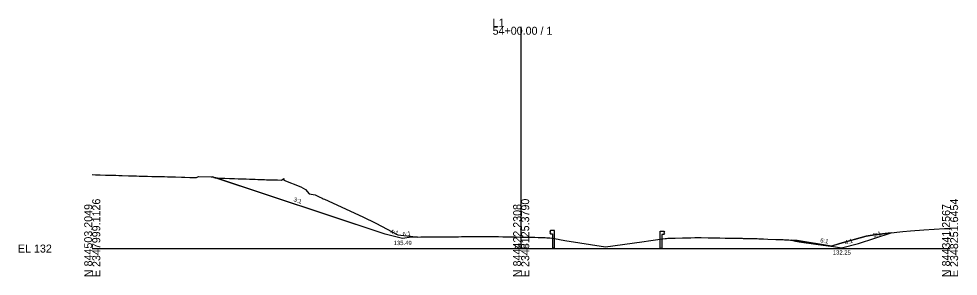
# Model space of a CAD drawing. Extents: x -26 to 2348258, y -10 to 844496.
# Drawn here: x 1275.5 to 1604, y 4990.3 to 5080.5 of the extents above; entities that cross this region are included whole.
import ezdxf

# ---------------------------------------------------------------- set-up
doc = ezdxf.new("R2010")
doc.units = 0
for name, color, linetype in [('Exist Cross Section Cell', 7, 'Continuous'), ('Exist XS Center Line Elevation Label', 7, 'Continuous'), ('Exist XS Ground Line', 7, 'Continuous'), ('Prop CMT Guardrail Graphics', 7, 'Continuous'), ('Prop CMT Slope Grass', 7, 'Continuous'), ('Prop XS Earthwork Shape', 7, 'Continuous'), ('Prop XS SE Text', 7, 'Continuous')]:
    doc.layers.add(name, color=color, linetype=linetype)

msp = doc.modelspace()

# ---------------------------------------------------------------- linework, layer by layer
at = {"layer": 'Exist Cross Section Cell'}
for p, q in [((1451.19, 5000), (1451.19, 5077.7)), ((1301.19, 5000), (1451.19, 5000)), ((1451.19, 5000), (1601.19, 5000))]:
    msp.add_line(p, q, dxfattribs=at)
at = {"layer": 'Exist XS Ground Line'}
msp.add_lwpolyline([(1301.19, 5025.9), (1302.3, 5025.85), (1302.75, 5025.84), (1303.97, 5025.8), (1305.82, 5025.75), (1307.57, 5025.71), (1308.7, 5025.68), (1309.39, 5025.66), (1310.47, 5025.63), (1311.67, 5025.6), (1313.87, 5025.52), (1315.06, 5025.48), (1316.61, 5025.44), (1317.58, 5025.41), (1318.36, 5025.39), (1319.12, 5025.37), (1320.55, 5025.34), (1322.02, 5025.3), (1323.51, 5025.27), (1323.85, 5025.26), (1324.37, 5025.25), (1326.51, 5025.2), (1327.46, 5025.16), (1328.95, 5025.12), (1329.46, 5025.1), (1330.36, 5025.07), (1332.44, 5025.01), (1332.87, 5025.01), (1333.61, 5024.99), (1335.35, 5024.95), (1336.61, 5024.93), (1337.2, 5024.93), (1337.68, 5024.92), (1338.32, 5025.25), (1342.79, 5025.16), (1343.47, 5025.14), (1344.16, 5024.73), (1344.95, 5024.72), (1345.83, 5024.69), (1347.51, 5024.62), (1349.18, 5024.56), (1350.22, 5024.53), (1350.97, 5024.51), (1352.17, 5024.47), (1353.19, 5024.43), (1355.01, 5024.38), (1356.15, 5024.35), (1356.77, 5024.32), (1358.22, 5024.27), (1359.14, 5024.24), (1361.41, 5024.15), (1362.1, 5024.12), (1363.63, 5024.08), (1365.07, 5024.04), (1365.92, 5024.03), (1367.37, 5024.01), (1368.19, 5024.6), (1368.2, 5023.99), (1374.1, 5021.58), (1375.79, 5020.64), (1377.02, 5019.23), (1379.2, 5018.83), (1380.56, 5018.15), (1381.55, 5017.65), (1382, 5017.45), (1382.36, 5017.27), (1395.77, 5011.07), (1400.35, 5008.86), (1408.08, 5004.81), (1413.27, 5004.27), (1414.88, 5004.03), (1416.15, 5004.06), (1417, 5004.07), (1418.56, 5004.08), (1421.6, 5004.1), (1424.54, 5004.12), (1425.19, 5004.12), (1426.32, 5004.13), (1427.21, 5004.14), (1427.57, 5004.14), (1429.28, 5004.16), (1430.37, 5004.17), (1430.92, 5004.17), (1432.41, 5004.19), (1433.41, 5004.19), (1435.51, 5004.2), (1436.4, 5004.21), (1437.84, 5004.22), (1439.78, 5004.21), (1440.82, 5004.2), (1442.28, 5004.19), (1443.25, 5004.17), (1444.77, 5004.15), (1445.27, 5004.15), (1446.14, 5004.13), (1448.22, 5004.08), (1449.43, 5004.06), (1450.87, 5004.03), (1451.27, 5004.02), (1454.16, 5003.97), (1455.91, 5003.94), (1457.14, 5003.91), (1457.74, 5003.9), (1458.72, 5003.87), (1459.57, 5003.84), (1460.16, 5003.81), (1461.19, 5003.78), (1464.16, 5003.26), (1464.54, 5003.19), (1466.41, 5002.87), (1480.64, 5000.55), (1493.41, 5002.41), (1496.53, 5002.84), (1498.17, 5003.1), (1501.53, 5003.57), (1502.01, 5003.56), (1502.47, 5003.59), (1502.93, 5003.61), (1504.76, 5003.66), (1505.08, 5003.67), (1507.61, 5003.74), (1508.42, 5003.76), (1509.72, 5003.79), (1510.25, 5003.8), (1510.58, 5003.8), (1511.92, 5003.82), (1513.15, 5003.82), (1513.75, 5003.82), (1514.18, 5003.82), (1516.59, 5003.8), (1518.84, 5003.77), (1519.54, 5003.75), (1520.71, 5003.73), (1522.49, 5003.7), (1523.79, 5003.66), (1524.12, 5003.66), (1525.46, 5003.64), (1526.5, 5003.62), (1528.45, 5003.59), (1528.86, 5003.58), (1531.37, 5003.53), (1531.89, 5003.51), (1532.82, 5003.49), (1533.78, 5003.47), (1534.36, 5003.45), (1535.89, 5003.44), (1537.49, 5003.34), (1540.26, 5003.23), (1540.94, 5003.2), (1542.09, 5003.15), (1542.85, 5003.12), (1543.29, 5003.1), (1544.74, 5003.03), (1545.35, 5003), (1545.71, 5002.99), (1547.12, 5002.64), (1548.45, 5002.31), (1555.05, 5001.41), (1559.49, 5000.79), (1562.66, 5001.75), (1571.82, 5004.31), (1575.43, 5004.96), (1584.71, 5006), (1587.31, 5006.26), (1591.97, 5006.54), (1599.19, 5007.02), (1601.19, 5007.05)], dxfattribs=at)
at = {"layer": 'Prop CMT Guardrail Graphics'}
for p, q in [((1461.46, 5006.28), (1461.19, 5005.99)), ((1461.19, 5005.99), (1461.46, 5005.7)), ((1461.46, 5005.7), (1461.19, 5005.41)), ((1461.19, 5005.41), (1461.46, 5005.11)), ((1462.79, 5006.28), (1461.46, 5006.28)), ((1461.46, 5005.11), (1462.13, 5005.11)), ((1462.13, 5005.11), (1462.13, 5000.28)), ((1462.79, 5000.28), (1462.79, 5006.28)), ((1499.77, 5000.04), (1499.77, 5006.04)), ((1499.77, 5006.04), (1501.1, 5006.04)), ((1501.1, 5004.88), (1500.43, 5004.88)), ((1500.43, 5004.88), (1500.43, 5000.04)), ((1501.1, 5006.04), (1501.37, 5005.75)), ((1501.37, 5005.75), (1501.1, 5005.46)), ((1501.1, 5005.46), (1501.37, 5005.17)), ((1501.37, 5005.17), (1501.1, 5004.88)), ((1462.13, 5000.28), (1462.79, 5000.28)), ((1500.43, 5000.04), (1499.77, 5000.04))]:
    msp.add_line(p, q, dxfattribs=at)
at = {"layer": 'Prop CMT Slope Grass'}
for p, q in [((1403.65, 5004.99), (1343.17, 5025.15)), ((1409.65, 5003.49), (1403.65, 5004.99)), ((1412.88, 5004.03), (1409.65, 5003.49)), ((1414.88, 5004.03), (1412.88, 5004.03)), ((1569.21, 5001.75), (1580.55, 5005.53)), ((1545.71, 5002.99), (1547.71, 5002.83)), ((1547.71, 5002.83), (1563.21, 5000.25)), ((1563.21, 5000.25), (1569.21, 5001.75))]:
    msp.add_line(p, q, dxfattribs=at)
at = {"layer": 'Prop XS Earthwork Shape'}
for points in [[(1343.47, 5025.14), (1343.83, 5024.93), (1343.17, 5025.15)], [(1344.16, 5024.73), (1344.43, 5024.73), (1343.83, 5024.93)], [(1355.01, 5024.38), (1356.15, 5024.35), (1356.77, 5024.32), (1358.22, 5024.27), (1359.14, 5024.24), (1361.41, 5024.15), (1362.1, 5024.12), (1363.63, 5024.08), (1365.07, 5024.04), (1365.92, 5024.03), (1367.37, 5024.01), (1368.19, 5024.6), (1368.2, 5023.99), (1374.1, 5021.58), (1375.79, 5020.64), (1377.02, 5019.23), (1379.2, 5018.83), (1380.56, 5018.15), (1381.55, 5017.65), (1382, 5017.45), (1382.36, 5017.27), (1395.77, 5011.07), (1400.35, 5008.86), (1408.08, 5004.81), (1413.27, 5004.27), (1414.88, 5004.03), (1412.88, 5004.03), (1409.65, 5003.49), (1403.65, 5004.99), (1344.43, 5024.73), (1344.95, 5024.72), (1345.83, 5024.69), (1347.51, 5024.62), (1349.18, 5024.56), (1350.22, 5024.53), (1350.97, 5024.51), (1352.17, 5024.47), (1353.19, 5024.43)], [(1569.21, 5001.75), (1580.55, 5005.53), (1575.43, 5004.96), (1571.82, 5004.31), (1562.66, 5001.75), (1559.66, 5000.84), (1563.21, 5000.25)], [(1548.45, 5002.31), (1555.05, 5001.41), (1559.49, 5000.79), (1559.66, 5000.84), (1547.71, 5002.83), (1545.71, 5002.99), (1547.12, 5002.64)]]:
    msp.add_lwpolyline(points, close=True, dxfattribs=at)

# ---------------------------------------------------------------- texts
at = {"layer": 'Exist Cross Section Cell'}
for s, p in [('L1', (1441.19, 5077.7)), ('54+00.00 / 1', (1441.19, 5074.9)), ('EL 132', (1275.19, 4998.6))]:
    msp.add_text(s, height=2.8, dxfattribs=at).set_placement(p)
for s, p in [('E 2347999.1126', (1303.99, 4990)), ('E 2348125.3790', (1453.99, 4990)), ('E 2348251.6454', (1603.99, 4990)), ('N 844503.2049', (1301.19, 4990)), ('N 844422.2308', (1451.19, 4990)), ('N 844341.2567', (1601.19, 4990))]:
    msp.add_text(s, height=2.8, rotation=90, dxfattribs=at).set_placement(p)
at = {"layer": 'Exist XS Center Line Elevation Label'}
msp.add_text('136.02', height=1.2, dxfattribs=at).set_placement((1448.67, 5000.23))
at = {"layer": 'Prop XS SE Text'}
for s, rotation, p in [('3:1', 341.5651, (1371.48, 5016.59)), ('4:1', 345.9638, (1405.29, 5005.33)), ('6:1', 9.4623, (1409.84, 5004.2)), ('6:1', 350.5377, (1555.7, 5002.23)), ('3:1', 18.4349, (1574.51, 5003.84)), ('4:1', 14.0362, (1564.52, 5001.38))]:
    msp.add_text(s, height=1.5, rotation=rotation, dxfattribs=at).set_placement(p)
for s, p in [('135.49', (1406.58, 5001.21)), ('132.25', (1560.15, 4997.89))]:
    msp.add_text(s, height=1.5, dxfattribs=at).set_placement(p)

doc.saveas('drawing.dxf')
